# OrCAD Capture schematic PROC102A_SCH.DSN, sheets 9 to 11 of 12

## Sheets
9 10.SMART SWITCH: size C; title: SMART SWITCH
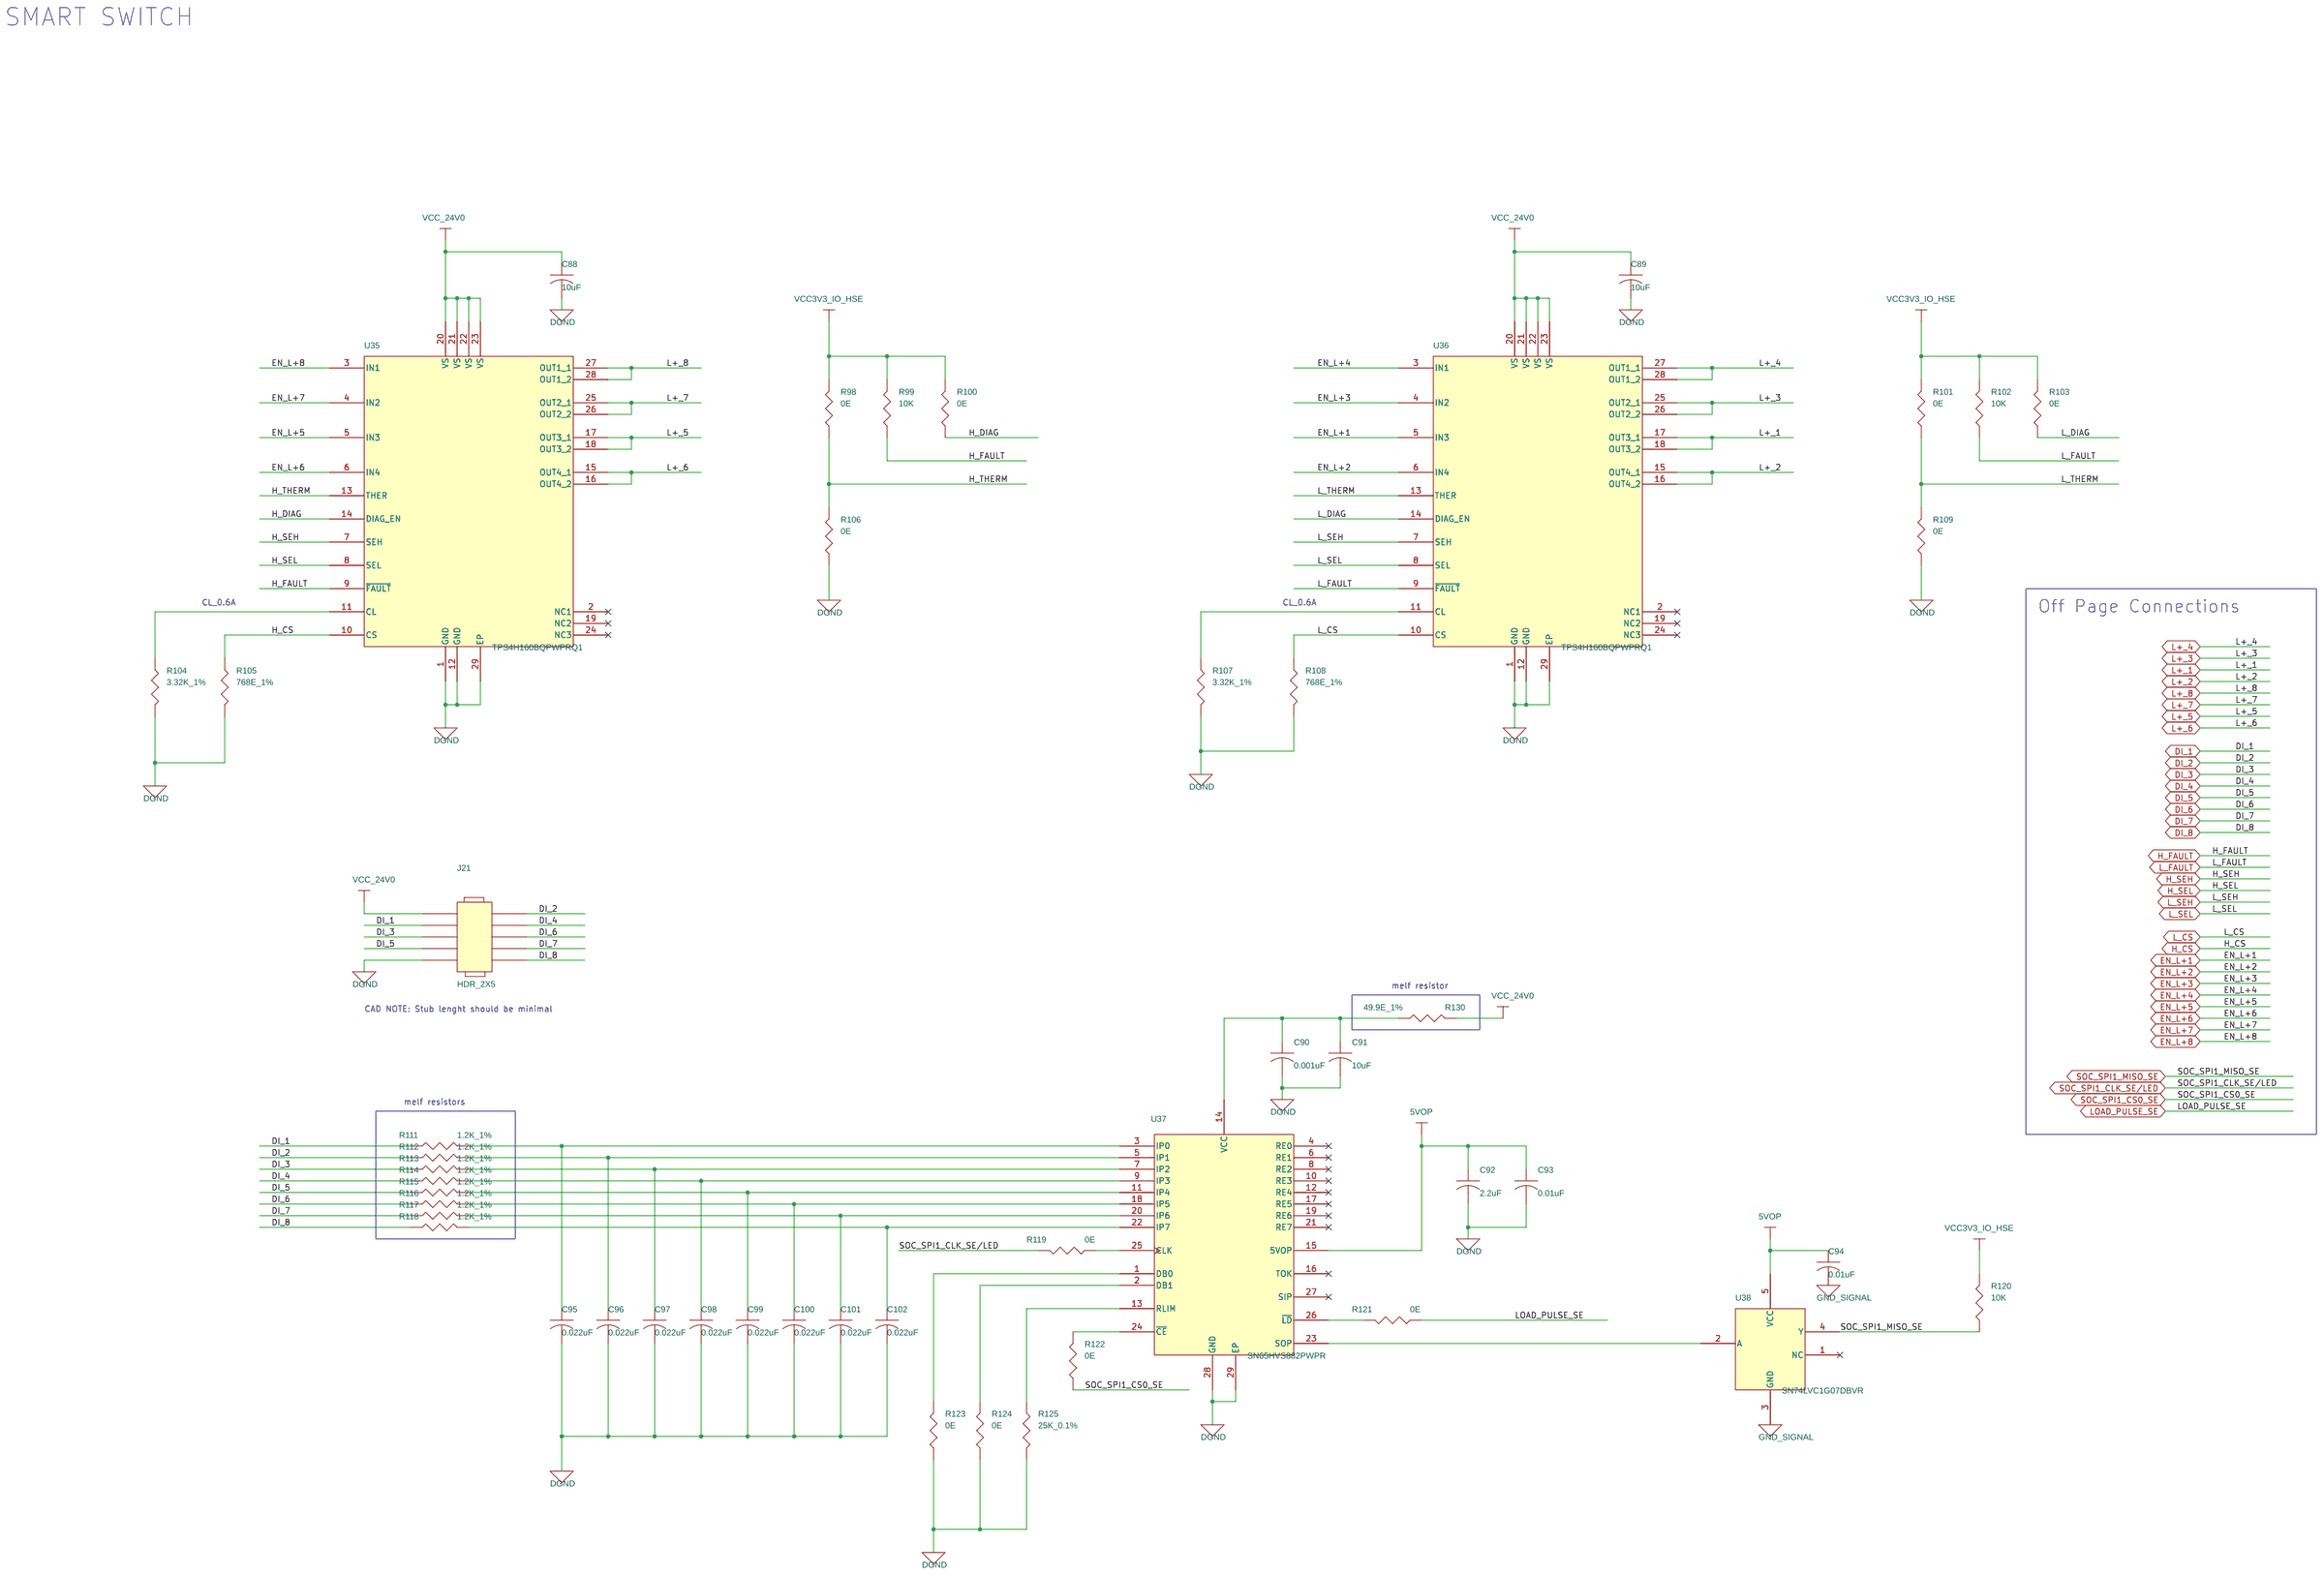
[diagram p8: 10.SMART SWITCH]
10 11.POWER AND ADC SECTION.: size C; title: POWER AND ADC SECTION
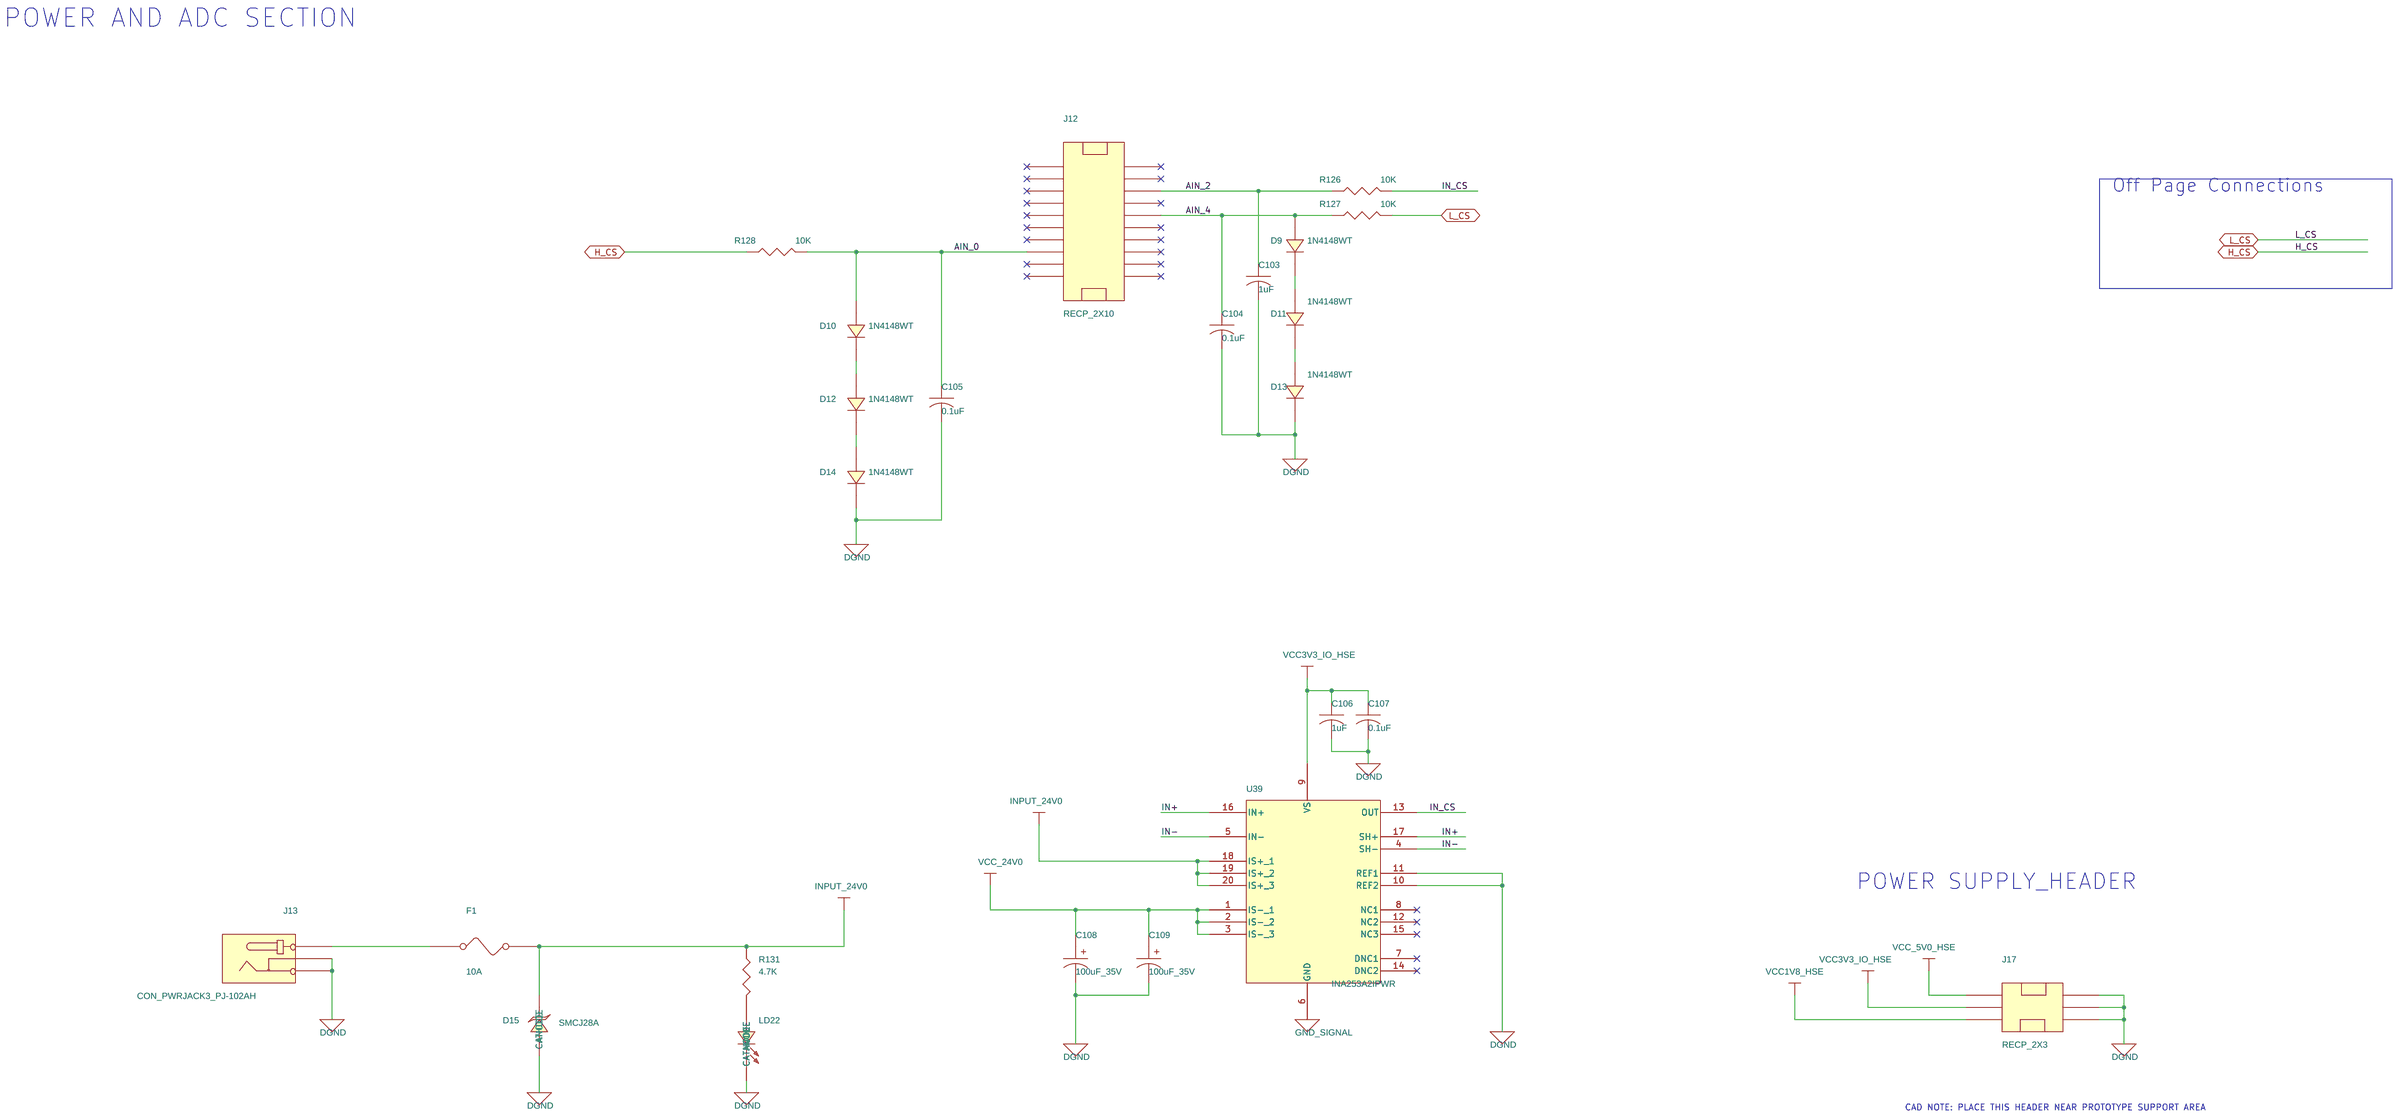
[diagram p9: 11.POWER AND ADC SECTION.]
11 08.IO LINK TRANCIEVER[1:4]: size C; title: IO LINK TRANCIEVER[1:4]
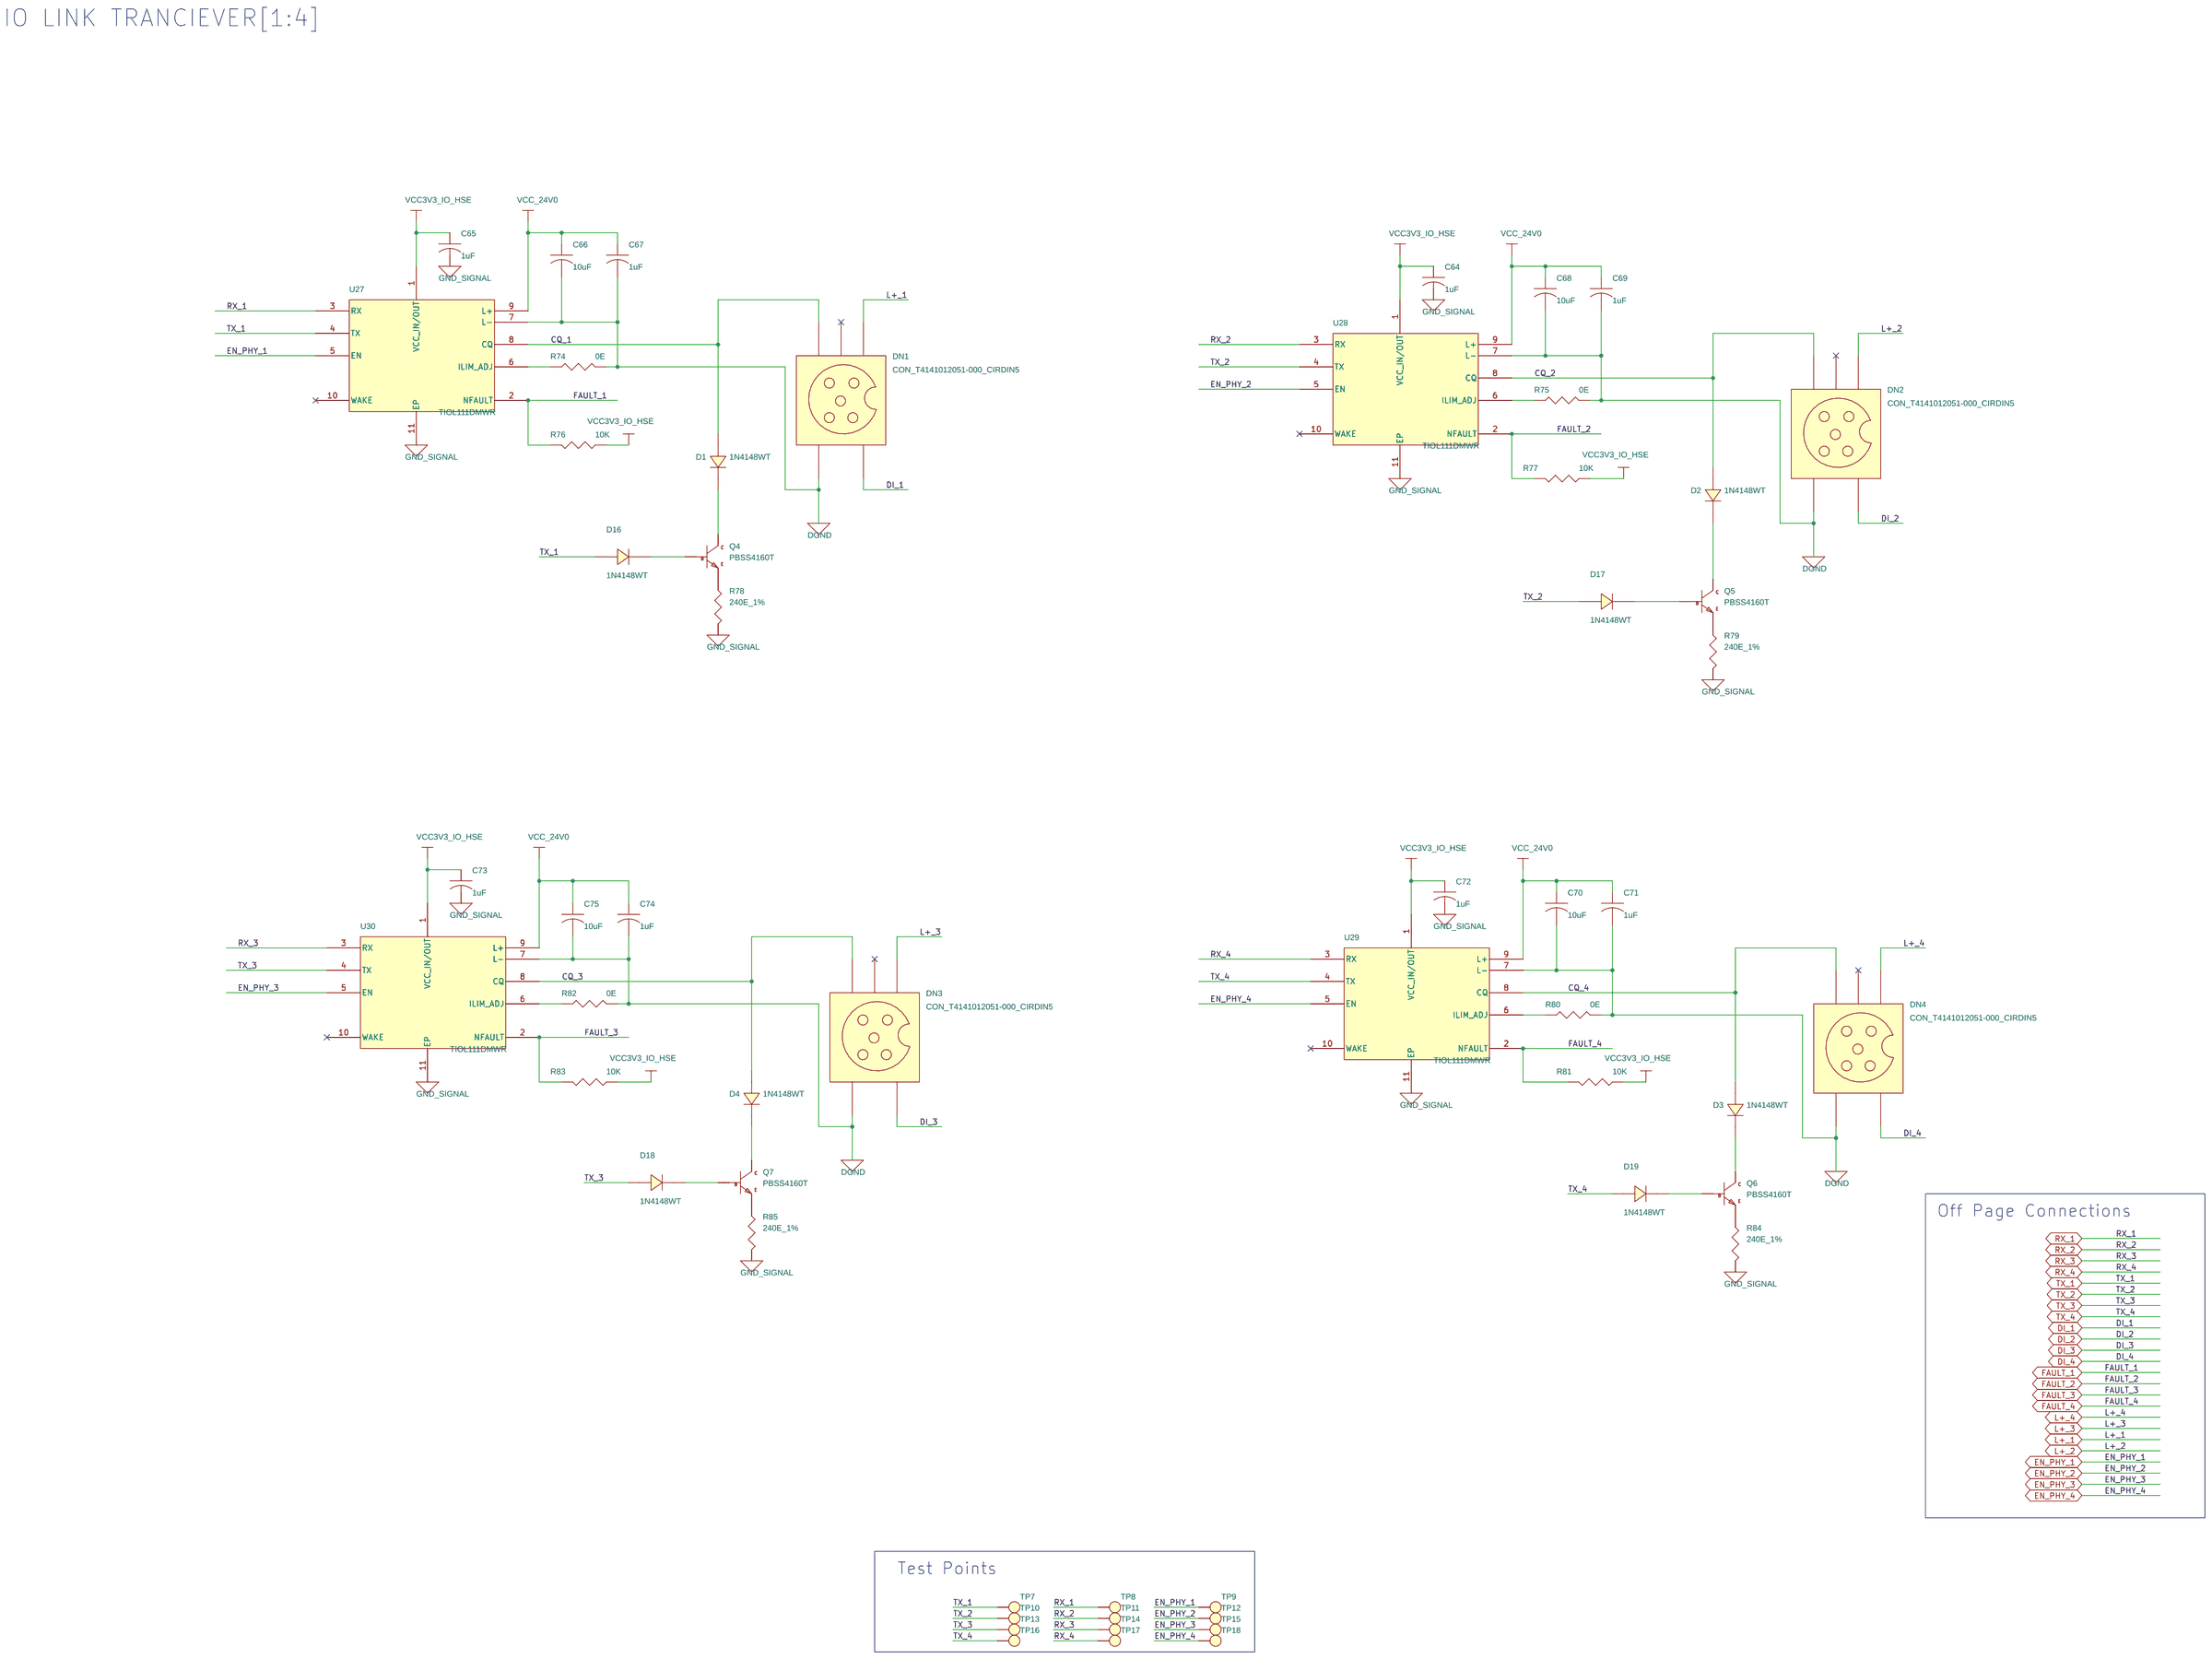
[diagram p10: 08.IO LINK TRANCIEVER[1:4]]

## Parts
sheet 08.IO LINK TRANCIEVER[1:4]
C64  1uF  [CAP0402_0-75]
C65  1uF  [CAP0402_0-75]
C66  10uF  [CAP1206_2]
C67  1uF  [CAP0805_1-5]
C68  10uF  [CAP1206_2]
C69  1uF  [CAP0805_1-5]
C70  10uF  [CAP1206_2]
C71  1uF  [CAP0805_1-5]
C72  1uF  [CAP0402_0-75]
C73  1uF  [CAP0402_0-75]
C74  1uF  [CAP0805_1-5]
C75  10uF  [CAP1206_2]
D1  1N4148WT  [DIO_SOD523]
D2  1N4148WT  [DIO_SOD523]
D3  1N4148WT  [DIO_SOD523]
D4  1N4148WT  [DIO_SOD523]
D16  1N4148WT  [DIO_SOD523]
D17  1N4148WT  [DIO_SOD523]
D18  1N4148WT  [DIO_SOD523]
D19  1N4148WT  [DIO_SOD523]
DN1  CON_T4141012051-000_CIRDIN5  [CON_CIRDIN5_T4141012051_S_S_T_23]
DN2  CON_T4141012051-000_CIRDIN5  [CON_CIRDIN5_T4141012051_S_S_T_23]
DN3  CON_T4141012051-000_CIRDIN5  [CON_CIRDIN5_T4141012051_S_S_T_23]
DN4  CON_T4141012051-000_CIRDIN5  [CON_CIRDIN5_T4141012051_S_S_T_23]
Q4  PBSS4160T  [SOT23-123_1-1]
Q5  PBSS4160T  [SOT23-123_1-1]
Q6  PBSS4160T  [SOT23-123_1-1]
Q7  PBSS4160T  [SOT23-123_1-1]
R74  0E  [RES0402_0-5]
R75  0E  [RES0402_0-5]
R76  10K  [RES0402_0-5]
R77  10K  [RES0402_0-5]
R78  240E_1%  [RES0402_0-5]
R79  240E_1%  [RES0402_0-5]
R80  0E  [RES0402_0-5]
R81  10K  [RES0402_0-5]
R82  0E  [RES0402_0-5]
R83  10K  [RES0402_0-5]
R84  240E_1%  [RES0402_0-5]
R85  240E_1%  [RES0402_0-5]
TP7  TP20_SMD  [TP20_SMD]
TP8  TP20_SMD  [TP20_SMD]
TP9  TP20_SMD  [TP20_SMD]
TP10  TP20_SMD  [TP20_SMD]
TP11  TP20_SMD  [TP20_SMD]
TP12  TP20_SMD  [TP20_SMD]
TP13  TP20_SMD  [TP20_SMD]
TP14  TP20_SMD  [TP20_SMD]
TP15  TP20_SMD  [TP20_SMD]
TP16  TP20_SMD  [TP20_SMD]
TP17  TP20_SMD  [TP20_SMD]
TP18  TP20_SMD  [TP20_SMD]
U27  TIOL111DMWR  [VSON10_19-68_120X100_1]
U28  TIOL111DMWR  [VSON10_19-68_120X100_1]
U29  TIOL111DMWR  [VSON10_19-68_120X100_1]
U30  TIOL111DMWR  [VSON10_19-68_120X100_1]
sheet 10.SMART SWITCH
C88  10uF  [CAP1206_2]
C89  10uF  [CAP1206_2]
C90  0.001uF  [CAP0805_1]
C91  10uF  [CAP1206_2]
C92  2.2uF  [CAP0805_1-5]
C93  0.01uF  [CAP0402_0-75]
C94  0.01uF  [CAP0402_0-75]
C95  0.022uF  [CAP0603_1]
C96  0.022uF  [CAP0603_1]
C97  0.022uF  [CAP0603_1]
C98  0.022uF  [CAP0603_1]
C99  0.022uF  [CAP0603_1]
C100  0.022uF  [CAP0603_1]
C101  0.022uF  [CAP0603_1]
C102  0.022uF  [CAP0603_1]
J21  HDR_2X5  [HDR_5X2_100_S_T_8-6]
R98  0E  [RES0402_0-5]
R99  10K  [RES0402_0-5]
R100  0E  [RES0402_0-5]
R101  0E  [RES0402_0-5]
R102  10K  [RES0402_0-5]
R103  0E  [RES0402_0-5]
R104  3.32K_1%  [RES0402_0-5]
R105  768E_1%  [RES0402_0-5]
R106  0E  [RES0402_0-5]
R107  3.32K_1%  [RES0402_0-5]
R108  768E_1%  [RES0402_0-5]
R109  0E  [RES0402_0-5]
R111  1.2K_1%  [RES_MELF0102_1-1]
R112  1.2K_1%  [RES_MELF0102_1-1]
R113  1.2K_1%  [RES_MELF0102_1-1]
R114  1.2K_1%  [RES_MELF0102_1-1]
R115  1.2K_1%  [RES_MELF0102_1-1]
R116  1.2K_1%  [RES_MELF0102_1-1]
R117  1.2K_1%  [RES_MELF0102_1-1]
R118  1.2K_1%  [RES_MELF0102_1-1]
R119  0E  [RES0402_0-5]
R120  10K  [RES0402_0-5]
R121  0E  [RES0402_0-5]
R122  0E  [RES0402_0-5]
R123  0E  [RES0402_0-5]
R124  0E  [RES0402_0-5]
R125  25K_0.1%  [RES0402_1]
R130  49.9E_1%  [RES_MELF0102_1-1]
U35  TPS4H160BQPWPRQ1  [HTSSOP28_LM5175-Q1_180X390_1-2]
U36  TPS4H160BQPWPRQ1  [HTSSOP28_LM5175-Q1_180X390_1-2]
U37  SN65HVS882PWPR  [ETSSOP28_SN65HVS885_390X180_1-2]
U38  SN74LVC1G07DBVR  [SOT23-5]
sheet 11.POWER AND ADC SECTION.
C103  1uF  [CAP0402_0-75]
C104  0.1uF  [CAP0402_0-75]
C105  0.1uF  [CAP0402_0-75]
C106  1uF  [CAP0402_0-75]
C107  0.1uF  [CAP0402_0-75]
C108  100uF_35V  [CAPAE_DCASE_6-1]
C109  100uF_35V  [CAPAE_DCASE_6-1]
D9  1N4148WT  [DIO_SOD523]
D10  1N4148WT  [DIO_SOD523]
D11  1N4148WT  [DIO_SOD523]
D12  1N4148WT  [DIO_SOD523]
D13  1N4148WT  [DIO_SOD523]
D14  1N4148WT  [DIO_SOD523]
D15  SMCJ28A  [DIO_SMC]
F1  10A  [FUSE_397_410X110_SMD_2-9]
J12  RECP_2X10  [RECPT_2X10_68683-310_S_T_7-1]
J13  CON_PWRJACK3_PJ-102AH  [CON_PWRJACK3_PJ-102AH_P_R_T_11]
J17  RECP_2X3  [RECPT_2X3_PPTC032LFBN_S_T_8-5]
LD22  150060VS75000  [LED_150060SS75000_70X40_SMD_0-8]
R126  10K  [RES0603_0-5]
R127  10K  [RES0603_0-5]
R128  10K  [RES0603_0-5]
R131  4.7K  [RES0805_0-75]
U39  INA253A2IPWR  [TSSOP20_25-59_260X180_1-2]

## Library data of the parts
C64 C65 C72 C73 C103 C106 = CAP: CAP CERAMIC 1uF 10V 20% X5R 0402; Chkd/date: MANIRAJA/210820; Crtd /date: ALVY/190820; Custom_Duty: 15%; Customs_HS_Code: 85322990; Distributor_name: DIGIKEY; Distributor_part_number: 732-7489-1-ND; Footprint Path: Y:\MIS_DATABASE\Library\ALTIUM_TOOL\PCB_FOOTPRINTS\Altium_Footprint_Lib.PcbLib; Height: 0.55MM; Library Path: Y:\MIS_DATABASE\Library\ALTIUM_TOOL\SCHEMATICS_PARTS\MS_DISCRETE_Library.schlib; Mfr_name: WURTH ELECTRONICS; Mfr_part_number: 885012105012; Mistral Part No: 120020080009-R; Package: 0402; Part_type: CAPACITORS\CERAMIC; Project: AM64x_EVM_BRD; RoHS: RoHS; Temperature: -55°C+85°C; Tolerance: 20%; Voltage: 10V; Wattage: NA; Weight: 0.65mg; Datasheet: Y:\MIS_DATABASE\DATASHEETS\CAPACITORS\885012105012.PDF
C66 C68 C70 C75 C88 C89 C91 = CAP: CAP CERAMIC 10uF 50V 10% X5R AUTO 1206; Chkd/date: MANIRAJA/261018; Crtd /date: ALVY/261018; Custom_Duty: 15%; Customs_HS_Code: 85322990; Distributor_name: DIGIKEY; Distributor_part_number: 490-12456-1-ND; Footprint Path: Y:\MIS_DATABASE\Library\ALTIUM_TOOL\PCB_FOOTPRINTS\Altium_Footprint_Lib.PcbLib; Height: 1.80MM; Library Path: Y:\MIS_DATABASE\Library\ALTIUM_TOOL\SCHEMATICS_PARTS\MS_DISCRETE_Library.schlib; Mfr_name: MURATA; Mfr_part_number: GRT31CR61H106KE01L; Mistral Part No: 120011060019-R; Package: 1206; Part_type: CAPACITORS\CERAMIC; Project: LRDE_ABCMV2_MB; RoHS: RoHS; Temperature: -55°C+85°C; Tolerance: 10%; Voltage: 50V; Wattage: NA; Weight: 16.2mg; Datasheet: Y:\MIS_DATABASE\DATASHEETS\CAPACITORS\GRT31CR61H106KE01L.PDF
C67 C69 C71 C74 = CAP: CAP CERAMIC 1uF 50V 10% X7R 0805; Chkd/date: MANIRAJA/100920; Crtd /date: ALVY/100920; Custom_Duty: 15%; Customs_HS_Code: 85322990; Distributor_name: DIGIKEY; Distributor_part_number: 732-7678-1-ND; Footprint Path: Y:\MIS_DATABASE\Library\ALTIUM_TOOL\PCB_FOOTPRINTS\Altium_Footprint_Lib.PcbLib; Height: 1.35MM; Library Path: Y:\MIS_DATABASE\Library\ALTIUM_TOOL\SCHEMATICS_PARTS\MS_DISCRETE_Library.schlib; Mfr_name: WURTH ELECTRONICS; Mfr_part_number: 885012207103; Mistral Part No: 120011010018-R; Package: 0805; Part_type: CAPACITORS\CERAMIC; Project: AM64x-IO LINK BRD; RoHS: RoHS; Temperature: -55°C+125°C; Tolerance: 10%; Voltage: 50V; Wattage: NA; Weight: 36mg; Datasheet: Y:\MIS_DATABASE\DATASHEETS\CAPACITORS\885012207103.PDF
D1-D4 D9-D14 D16-D19 = DIODE: DIODE SWITCH 75V 10mA SOD523; Chkd/date: SUHAS/041010; Crtd /date: MAZHAR/110210; Custom_Duty: 15%; Customs_HS_Code: 85412900; Distributor_name: DIGIKEY; Distributor_part_number: 1N4148WTCT-ND; Height: 0.70MM; Mfr_name: FAIRCHILD; Mistral Part No: 130010020017-R; Package: SOD523; Part_type: DIODE\SWITCHING; Project: NPOL_PREAMP; RoHS: RoHS; Temperature: -55°C+150°C; Tolerance: 20%; Voltage: 75V; Weight: NA; Datasheet: Y:\MIS_DATABASE\DATASHEETS\DISCRETES\DIODES\1N4148WT-F.PDF
DN1-DN4 = CON_T4143012051_CIRDIN5_S: CON CIRCULAR 5POS FEMALE ST TH; Chkd/date: MANIRAJA/280820; Crtd /date: ALVY/280820; Custom_Duty: 24%; Customs_HS_Code: 85369090; Distributor_name: DIGIKEY; Distributor_part_number: A126851-ND; Footprint Path: Y:\MIS_DATABASE\Library\ALTIUM_TOOL\PCB_FOOTPRINTS\Altium_Footprint_Lib.PcbLib; Height: 23.00MM; Library Path: Y:\MIS_DATABASE\Library\ALTIUM_TOOL\SCHEMATICS_PARTS\MS_CONNECTOR_Library.schlib; Mfr_name: TE CONNECTIVITY; Mfr_part_number: T4141012051-000; Mistral Part No: 150020080008-R; Package: THRU-HOLE; Part_type: CONNECTOR\CIRDIN; Project: AM64x_EVM_TESTJIG_BRD; RoHS: RoHS; Temperature: -40°C+85°C; Tolerance: NA; Voltage: NA; Wattage: NA; Weight: 16500mg; Datasheet: Y:\MIS_DATABASE\DATASHEETS\CONNECTORS\T41410120X1-000.PDF
Q4-Q7 = NPN_123_SOT23-3: TRANSISTOR NPN 60V 1A SOT23-3; Chkd/date: MANIRAJA/220720; Crtd /date: ALVY/210720; Custom_Duty: 15%; Customs_HS_Code: 85412900; Distributor_name: DIGIKEY; Distributor_part_number: 1727-3939-1-ND; Footprint Path: Y:\MIS_DATABASE\Library\ALTIUM_TOOL\PCB_FOOTPRINTS\Altium_Footprint_Lib.PcbLib; Height: 1.10MM; Library Path: Y:\MIS_DATABASE\Library\ALTIUM_TOOL\SCHEMATICS_PARTS\MS_TRANSISTOR_Library.schlib; Mfr_name: NXP SEMICONDUCTORS; Mfr_part_number: PBSS4160T,215; Mistral Part No: 130020070017-R; Package: SOT23-3; Part_type: TRANSISTOR\BIPOLAR; Project: AM64x-IO LINK BRD; RoHS: RoHS; Temperature: -65°C+150°C; Tolerance: NA; Voltage: NA; Wattage: NA; Weight: 8mg; Datasheet: Y:\MIS_DATABASE\DATASHEETS\DISCRETES\TRANSISTORS_FETS\PBSS4160T.PDF
R74 R75 R80 R82 = RESISTOR: RES 0E 1/16W JUMPER 0402; Chkd/date: VASANTHA/201216; Crtd /date: MUDDU/190810; Custom_Duty: 15%; Customs_HS_Code: 85332119; Distributor_name: DIGIKEY; Distributor_part_number: 541-0.0JCT-ND; Footprint Path: Y:\MIS_DATABASE\Library\ALTIUM_TOOL\PCB_FOOTPRINTS\Altium_Footprint_Lib.PcbLib; Height: 0.40MM; Library Path: Y:\MIS_DATABASE\Library\ALTIUM_TOOL\SCHEMATICS_PARTS\MS_DISCRETE_Library.schlib; Mfr_name: VISHAY; Mfr_part_number: CRCW04020000Z0ED; Mistral Part No: 110010080019-R; Package: 0402; Part_type: RESISTORS\FIXED; Project: PB_BUGBASE; RoHS: RoHS; Temperature: -55°C+155°C; Tolerance: NA; Voltage: NA; Wattage: 1/16W; Weight: 0.65mg; Datasheet: Y:\MIS_DATABASE\DATASHEETS\RESISTORS\CRCW0603.PDF
R76 R77 R81 R83 R99 R102 R120 = RESISTOR: RES 10K 1/16W 5% 0402; Chkd/date: VASANTHA/061216; Crtd /date: MAZHAR/230805; Custom_Duty: 15%; Customs_HS_Code: 85332119; Distributor_name: DIGIKEY; Distributor_part_number: 311-10KJRCT-ND; Footprint Path: Y:\MIS_DATABASE\Library\ALTIUM_TOOL\PCB_FOOTPRINTS\Altium_Footprint_Lib.PcbLib; Height: 0.40MM; Library Path: Y:\MIS_DATABASE\Library\ALTIUM_TOOL\SCHEMATICS_PARTS\MS_DISCRETE_Library.schlib; Mfr_name: YAGEO AMERICA; Mfr_part_number: RC0402JR-0710KL; Mistral Part No: 110011060021-R; Package: 0402; Part_type: RESISTORS\FIXED; Project: HSE; RoHS: RoHS; Temperature: -55°C+155°C; Tolerance: 5%; Voltage: NA; Wattage: 1/16W; Weight: 0.65mg; Datasheet: Y:\MIS_DATABASE\DATASHEETS\RESISTORS\RCXXXXL-SER_MAR18.PDF
R78 R79 R84 R85 = RESISTOR: RES 240E 1/10W 1% 0402; Chkd/date: MAZHAR/150611; Crtd /date: BAVISH/020611; Custom_Duty: 15%; Customs_HS_Code: 85332119; Distributor_name: DIGIKEY; Distributor_part_number: P240LCT-ND; Footprint Path: Y:\MIS_DATABASE\Library\ALTIUM_TOOL\PCB_FOOTPRINTS\Altium_Footprint_Lib.PcbLib; Height: 0.40MM; Library Path: Y:\MIS_DATABASE\Library\ALTIUM_TOOL\SCHEMATICS_PARTS\MS_DISCRETE_Library.schlib; Mfr_name: PANASONIC-ECG; Mfr_part_number: ERJ-2RKF2400X; Mistral Part No: 110011060017-R; Package: 0402; Part_type: RESISTORS\FIXED; Project: AM4515_EVM_LCD; RoHS: RoHS; Temperature: -55°C+155°C; Tolerance: 1%; Voltage: NA; Wattage: 1/10W; Weight: 0.8mg; Datasheet: Y:\MIS_DATABASE\DATASHEETS\RESISTORS\PAN-ERJSER_NOV17.PDF
TP7-TP18 = TESTPOINT: TESTPOINT CIR 20 SMD; Chkd/date: SHREESHAIL/171006; Crtd /date: MAZHAR/171006; Custom_Duty: NA; Customs_HS_Code: NA; Distributor_name: NA; Distributor_part_number: NA; Footprint Path: Y:\MIS_DATABASE\Library\ALTIUM_TOOL\PCB_FOOTPRINTS\Altium_Footprint_Lib.PcbLib; Height: NA; Library Path: Y:\MIS_DATABASE\Library\ALTIUM_TOOL\SCHEMATICS_PARTS\MS_DISCRETE_Library.schlib; MECHANICAL 3D STEP FILE: NA; Mfr_name: LOCAL; Mistral Part No: NA; Package: SMD; Project: BT MODULE_CSRBC04; RoHS: NA; Temperature: NA; Tolerance: NA; Voltage: NA; Wattage: NA; Weight: NA; Datasheet: NA
U27-U30 = TIOL111_VSON10: IC IO-LINK DEVICE TRANSCEIVER WITH INTEGRATED SURGE PROTECTION VSON10; Chkd/date: MANIRAJA/210720; Crtd /date: ALVY/170720; Custom_Duty: 15%; Customs_HS_Code: 85423100; Distributor_name: DIGIKEY; Distributor_part_number: 296-49943-1-ND; Footprint Path: Y:\MIS_DATABASE\Library\ALTIUM_TOOL\PCB_FOOTPRINTS\Altium_Footprint_Lib.PcbLib; Height: 1.00MM; Library Path: Y:\MIS_DATABASE\Library\ALTIUM_TOOL\SCHEMATICS_PARTS\MS_MISCINTERFACE_Library.schlib; Mfr_name: TEXAS INSTRUMENTS; Mistral Part No: 141020070002-R; Package: VSON10; Part_type: ICS\INTERFACE\TRANSCEIVER; Project: AM64x-GP_EVM BRD; RoHS: RoHS; Temperature: -40°C+125°C; Tolerance: NA; Voltage: NA; Wattage: NA; Weight: 19mg; Datasheet: Y:\MIS_DATABASE\DATASHEETS\ICS\DIGITAL\BUSTRANSCEIVER\TIOL111.PDF
C90 = CAP: CAP CER 1000PF 50V X7R 0805; Chkd/date: USMAN/100812; Crtd /date: CHAITHANYA/080812; Custom_Duty: 15%; Customs_HS_Code: 85322990; Distributor_name: NA; Distributor_part_number: NA; Footprint Path: Y:\MIS_DATABASE\Library\ALTIUM_TOOL\PCB_FOOTPRINTS\Altium_Footprint_Lib.PcbLib; Height: 0.88MM; Library Path: Y:\MIS_DATABASE\Library\ALTIUM_TOOL\SCHEMATICS_PARTS\MS_DISCRETE_Library.schlib; Mfr_name: YAGEO AMERICA; Mfr_part_number: CC0805KRX7R9BB102; Mistral Part No: 120012080013-R; Package: 0805; Part_type: CAPACITORS\CERAMIC; Project: NPOL_FEP; RoHS: RoHS; Temperature: -55°C+125°C; Tolerance: 10%; Voltage: 50V; Wattage: NA; Weight: 5.5mg; Datasheet: Y:\MIS_DATABASE\DATASHEETS\CAPACITORS\C0603T-X7R-SER.PDF
C92 = CAP: CAP CERAMIC 2.2uF 25V 10% X7R 0805; Chkd/date: MANIRAJA/170820; Crtd /date: ALVY/170820; Custom_Duty: 15%; Customs_HS_Code: 85322990; Distributor_name: DIGIKEY; Distributor_part_number: 732-7673-1-ND; Footprint Path: Y:\MIS_DATABASE\Library\ALTIUM_TOOL\PCB_FOOTPRINTS\Altium_Footprint_Lib.PcbLib; Height: 1.45MM; Library Path: Y:\MIS_DATABASE\Library\ALTIUM_TOOL\SCHEMATICS_PARTS\MS_DISCRETE_Library.schlib; Mfr_name: WURTH ELECTRONICS; Mfr_part_number: 885012207079; Mistral Part No: 120009090012-R; Package: 0805; Part_type: CAPACITORS\CERAMIC; Project: AM64x_EVM_BRD; RoHS: RoHS; Temperature: -55°C+125°C; Tolerance: 10%; Voltage: 25V; Wattage: NA; Weight: 5.5mg; Datasheet: Y:\MIS_DATABASE\DATASHEETS\CAPACITORS\885012207079.PDF
C93 C94 = CAP: CAP CERAMIC 0.01uF 25V 10% X7R 0402; Chkd/date: MANIRAJA/170820; Crtd /date: ALVY/170820; Custom_Duty: 15%; Customs_HS_Code: 85322990; Distributor_name: DIGIKEY; Distributor_part_number: 732-7545-1-ND; Footprint Path: Y:\MIS_DATABASE\Library\ALTIUM_TOOL\PCB_FOOTPRINTS\Altium_Footprint_Lib.PcbLib; Height: 0.55MM; Library Path: Y:\MIS_DATABASE\Library\ALTIUM_TOOL\SCHEMATICS_PARTS\MS_DISCRETE_Library.schlib; Mfr_name: WURTH ELECTRONICS; Mfr_part_number: 885012205050; Mistral Part No: 120011090040-R; Package: 0402; Part_type: CAPACITORS\CERAMIC; Project: AM64x_EVM_BRD; RoHS: RoHS; Temperature: -55°C+125°C; Tolerance: 10%; Voltage: 25V; Wattage: NA; Weight: 0.65mg; Datasheet: Y:\MIS_DATABASE\DATASHEETS\CAPACITORS\885012205050.PDF
C95-C102 = CAP: CAP CERAMIC 0.022uF 100V 10% X7R 0603; Chkd/date: MAZHAR/280508; Crtd /date: USMAN/200508; Custom_Duty: 15%; Customs_HS_Code: 85322990; Distributor_name: DIGIKEY; Distributor_part_number: 490-3284-1-ND; Footprint Path: Y:\MIS_DATABASE\Library\ALTIUM_TOOL\PCB_FOOTPRINTS\Altium_Footprint_Lib.PcbLib; Height: 0.90MM; Library Path: Y:\MIS_DATABASE\Library\ALTIUM_TOOL\SCHEMATICS_PARTS\MS_DISCRETE_Library.schlib; Mfr_name: MURATA; Mfr_part_number: GRM188R72A223KAC4D; Mistral Part No: 120009030035-R; Package: 0603; Part_type: CAPACITORS\CERAMIC; Project: KMB; RoHS: RoHS; Temperature: -55°C+125°C; Tolerance: 10%; Voltage: 100V; Wattage: NA; Weight: 6.3mg; Datasheet: Y:\MIS_DATABASE\DATASHEETS\CAPACITORS\GRM188R72A223KAC4D.PDF
J21 = HEADER_5X2: CON HDR 2X5 2.54MM PITCH ST TH; Chkd/date: VASANTHA/220317; Crtd /date: MANIRAJA/210317; Custom_Duty: 24%; Customs_HS_Code: 85369090; Distributor_name: DIGIKEY; Distributor_part_number: 609-3243-ND; Height: 8.58MM; Mfr_name: FCI; Mfr_part_number: 67997-410HLF; Mistral Part No: 150015100040-R; Package: THRU-HOLE; Part_type: CONNECTOR\HEADERS; Project: CYPHY_ROADKILL; RoHS: RoHS; Temperature: NA; Tolerance: NA; Voltage: NA; Wattage: NA; Weight: NA; Datasheet: Y:\MIS_DATABASE\DATASHEETS\CONNECTORS\67997.PDF
R98 R100 R101 R103 R106 R109 R119 R121-R124 = RESISTOR: RES 0E 1/16W JUMPER 0402; Chkd/date: VASANTHA/201216; Crtd /date: MUDDU/190810; Custom_Duty: 15%; Customs_HS_Code: 85332119; Distributor_name: DIGIKEY; Distributor_part_number: 541-0.0JCT-ND; Footprint Path: Y:\MIS_DATABASE\Library\ALTIUM_TOOL\PCB_FOOTPRINTS\Altium_Footprint_Lib.PcbLib; Height: 0.40MM; Library Path: Y:\MIS_DATABASE\Library\ALTIUM_TOOL\SCHEMATICS_PARTS\MS_DISCRETE_Library.schlib; Mfr_name: VISHAY; Mfr_part_number: CRCW04020000Z0ED; Mistral Part No: 110010080019-R; Package: 0402; Part_type: RESISTORS\FIXED; Project: PB_BUGBASE; RoHS: RoHS; SIGNAL_MODEL: RESISTOR_RES0402_22E_1%_22E_1%; Temperature: -55°C+155°C; Tolerance: NA; Voltage: NA; Wattage: 1/16W; Weight: 0.65mg; Datasheet: Y:\MIS_DATABASE\DATASHEETS\RESISTORS\CRCW0603.PDF
R104 R107 = RESISTOR: RES 3.32K 1/10W 1% 0402; Chkd/date: MANIRAJA/190619; Crtd /date: ALVY/180619; Custom_Duty: 15%; Customs_HS_Code: 85332119; Distributor_name: DIGIKEY; Distributor_part_number: P3.32KLCT-ND; Footprint Path: Y:\MIS_DATABASE\Library\ALTIUM_TOOL\PCB_FOOTPRINTS\Altium_Footprint_Lib.PcbLib; Height: 0.40MM; Library Path: Y:\MIS_DATABASE\Library\ALTIUM_TOOL\SCHEMATICS_PARTS\MS_DISCRETE_Library.schlib; Mfr_name: PANASONIC-ECG; Mfr_part_number: ERJ-2RKF3321X; Mistral Part No: 110019060037-R; Package: 0402; Part_type: RESISTORS\FIXED; Project: BRUKER_SD820_COMMONDO; RoHS: RoHS; Temperature: -55°C+155°C; Tolerance: 1%; Voltage: NA; Wattage: 1/10W; Weight: 0.8mg; Datasheet: Y:\MIS_DATABASE\DATASHEETS\RESISTORS\PAN-ERJSER_NOV17.PDF
R105 R108 = RESISTOR: RES 768E 1/10W 1% 0402; Chkd/date: SUHAS/270910; Crtd /date: MAZHAR/161009; Custom_Duty: 15%; Customs_HS_Code: 85332119; Distributor_name: DIGIKEY; Distributor_part_number: P768LCT-ND; Footprint Path: Y:\MIS_DATABASE\Library\ALTIUM_TOOL\PCB_FOOTPRINTS\Altium_Footprint_Lib.PcbLib; Height: 0.40MM; Library Path: Y:\MIS_DATABASE\Library\ALTIUM_TOOL\SCHEMATICS_PARTS\MS_DISCRETE_Library.schlib; Mfr_name: PANASONIC-ECG; Mfr_part_number: ERJ-2RKF7680X; Mistral Part No: 110009100012-R; Package: 0402; Part_type: RESISTORS\FIXED; Project: BUG_BASE-II; RoHS: RoHS; Temperature: -55°C+155°C; Tolerance: 1%; Voltage: NA; Wattage: 1/10W; Weight: 0.8mg; Datasheet: Y:\MIS_DATABASE\DATASHEETS\RESISTORS\PAN-ERJSER_NOV17.PDF
R111-R118 = RESISTOR: RES 1.2K 0.3W 1% AUTO 0102 MELF; Chkd/date: JEBRAN/260315; Crtd /date: NAVEED/310714; Custom_Duty: 15%; Customs_HS_Code: 85332119; Distributor_name: DIGIKEY; Distributor_part_number: MMU-1.2KCCT-ND; Footprint Path: Y:\MIS_DATABASE\Library\ALTIUM_TOOL\PCB_FOOTPRINTS\Altium_Footprint_Lib.PcbLib; Height: 1.10MM; Library Path: Y:\MIS_DATABASE\Library\ALTIUM_TOOL\SCHEMATICS_PARTS\MS_DISCRETE_Library.schlib; Mfr_name: VISHAY; Mfr_part_number: MMU01020C1201FB300; Mistral Part No: 110014070066-R; Package: MELF; Part_type: RESISTORS\FIXED; Project: AGIS_POM; RoHS: RoHS; Temperature: -55°C+155°C; Tolerance: 1%; Voltage: NA; Wattage: 0.3W; Weight: 8mg; Datasheet: Y:\MIS_DATABASE\DATASHEETS\RESISTORS\MMU01020.PDF
R125 = RESISTOR: RES 25K 1/20W 0.1% 0402; Chkd/date: MANIRAJA/290719; Crtd /date: ALVY/290719; Custom_Duty: 15%; Customs_HS_Code: 85332119; Distributor_name: DIGIKEY; Distributor_part_number: 541-1903-1-ND; Footprint Path: Y:\MIS_DATABASE\Library\ALTIUM_TOOL\PCB_FOOTPRINTS\Altium_Footprint_Lib.PcbLib; Height: 0.84MM; Library Path: Y:\MIS_DATABASE\Library\ALTIUM_TOOL\SCHEMATICS_PARTS\MS_DISCRETE_Library.schlib; Mfr_name: VISHAY; Mfr_part_number: PNM0402E2502BST1; Mistral Part No: 110019070028-R; Package: 0402; Part_type: RESISTORS\FIXED; Project: NPOL_UAIS_LPA; RoHS: RoHS; Temperature: -55°C+155°C; Tolerance: 0.1%; Voltage: NA; Wattage: 1/20W; Weight: 120mg; Datasheet: Y:\MIS_DATABASE\DATASHEETS\RESISTORS\PNM_VISHAY-SEP18.PDF
R130 = RESISTOR: RES 49.9E 0.3W 1% AUTO 0102 MELF; Chkd/date: MANIRAJA/280720; Crtd /date: ALVY/240720; Custom_Duty: 15%; Customs_HS_Code: 85332119; Distributor_name: DIGIKEY; Distributor_part_number: MMU-49.9CCT-ND; Footprint Path: Y:\MIS_DATABASE\Library\ALTIUM_TOOL\PCB_FOOTPRINTS\Altium_Footprint_Lib.PcbLib; Height: 1.10MM; Library Path: Y:\MIS_DATABASE\Library\ALTIUM_TOOL\SCHEMATICS_PARTS\MS_DISCRETE_Library.schlib; Mfr_name: VISHAY; Mfr_part_number: MMU01020C4999FB300; Mistral Part No: 110020070019-R; Package: MELF; Part_type: RESISTORS\FIXED; Project: AM64x-IO LINK BRD; RoHS: RoHS; Temperature: -55°C+155°C; Tolerance: 1%; Voltage: NA; Wattage: 0.3W; Weight: 8mg; Datasheet: Y:\MIS_DATABASE\DATASHEETS\RESISTORS\MMU01020.PDF
U35 U36 = TPS4H160-Q1_HTSSOP28: IC 40V 160mE 4-CHANNEL SMART HIGH-SIDE SWITCH HTSSOP28; Chkd/date: MANIRAJA/210720; Crtd /date: ALVY/170720; Custom_Duty: 15%; Customs_HS_Code: 85423100; Distributor_name: DIGIKEY; Distributor_part_number: 296-44711-1-ND; Footprint Path: Y:\MIS_DATABASE\Library\ALTIUM_TOOL\PCB_FOOTPRINTS\Altium_Footprint_Lib.PcbLib; Height: 1.20MM; Library Path: Y:\MIS_DATABASE\Library\ALTIUM_TOOL\SCHEMATICS_PARTS\MS_MISCPOWER_Library.schlib; Mfr_name: TEXAS INSTRUMENTS; Mistral Part No: 142020070006-R; Package: HTSSOP28; Part_type: ICS\POWER; Project: AM64x-GP_EVM BRD; RoHS: RoHS; Temperature: -40°C+125°C; Tolerance: NA; Voltage: NA; Wattage: NA; Weight: 176.5mg; Datasheet: Y:\MIS_DATABASE\DATASHEETS\ICS\POWER\TPS4H160.PDF
U37 = SN65HVS882PWPR_HTSSOP28: IC 8-DIGITAL I/P SERIALIZER HTSSOP28; Chkd/date: MANIRAJA/280817; Crtd /date: MANIRAJA/280817; Custom_Duty: 15%; Customs_HS_Code: 85423100; Distributor_name: DIGIKEY; Distributor_part_number: 296-23432-1-ND; Height: 1.20MM; Mfr_name: TEXAS INSTRUMENTS; Mistral Part No: 141017080029-R; Package: HTSSOP28; Part_type: ICS\INTERFACE; Project: TI_MAXIE_CPB; RoHS: RoHS; Temperature: -40°C+125°C; Tolerance: NA; Voltage: NA; Wattage: NA; Weight: 118.5mg; Datasheet: Y:\MIS_DATABASE\DATASHEETS\ICS\INTERFACE\SN65HVS882.PDF
U38 = SN74LVC1G07DBVR_SOT23-5: IC SINGLE BUFFER/DRIVER SOT23-5; Chkd/date: MAZHAR/200208; Crtd /date: USMAN/200208; Custom_Duty: 15%; Customs_HS_Code: 85423100; Distributor_name: DIGIKEY; Distributor_part_number: 296-8485-1-ND; Footprint Path: Y:\MIS_DATABASE\Library\ALTIUM_TOOL\PCB_FOOTPRINTS\Altium_Footprint_Lib.PcbLib; Height: 1.45MM; Junction to Board °C/W: 62; Junction to Case °C/W: 164; Mfr_name: TEXAS INSTRUMENTS; Mistral Part No: 141009030405-R; Part_type: ICS\INTERFACE\LINE DRIVER; Project: MIB; RoHS: Sb/ Br FREE; Datasheet: Y:\MIS_DATABASE\DATASHEETS\ICS\INTERFACE\SN74LVC1G07.PDF
C104 C105 C107 = CAP: CAP CERAMIC 0.1uF 25V 20% X5R 0402; Alt_Mfr_name: YAGEO AMERICA; Alt_Mfr_part_number: CC0402KRX5R8BB104; Chkd/date: MANIRAJA/170820; Crtd /date: ALVY/170820; Custom_Duty: 15%; Customs_HS_Code: 85322990; Distributor_name: DIGIKEY; Distributor_part_number: 732-7495-1-ND; Footprint Path: Y:\MIS_DATABASE\Library\ALTIUM_TOOL\PCB_FOOTPRINTS\Altium_Footprint_Lib.PcbLib; Height: 0.55MM; Library Path: Y:\MIS_DATABASE\Library\ALTIUM_TOOL\SCHEMATICS_PARTS\MS_DISCRETE_Library.schlib; Mfr_name: WURTH ELECTRONICS; Mfr_part_number: 885012105018; Mistral Part No: 120020080003-R; Package: 0402; Part_type: CAPACITORS\CERAMIC; Project: AM64x_EVM_BRD; RoHS: RoHS; Temperature: -55°C+85°C; Tolerance: 20%; Voltage: 25V; Wattage: NA; Weight: 0.65mg; Datasheet: Y:\MIS_DATABASE\DATASHEETS\CAPACITORS\885012105018.PDF
C108 C109 = CAP_POL: CAP ELECTROLYTIC 100uF 35V 20% DCASE_6666; Chkd/date: MANIRAJA/280918; Crtd /date: ALVY/270918; Custom_Duty: 15%; Customs_HS_Code: 85322990; Distributor_name: DIGIKEY; Distributor_part_number: PCE5016CT-ND; Footprint Path: Y:\MIS_DATABASE\Library\ALTIUM_TOOL\PCB_FOOTPRINTS\Altium_Footprint_Lib.PcbLib; Height: 6.10MM; Library Path: Y:\MIS_DATABASE\Library\ALTIUM_TOOL\SCHEMATICS_PARTS\MS_DISCRETE_Library.schlib; Mfr_name: PANASONIC-ECG; Mfr_part_number: EEE-FT1V101AP; Mistral Part No: 120018090055-R; Package: DCASE_6666; Part_type: CAPACITORS\ELECTROLYTIC; Project: TI_J7_SVB-DUT; RoHS: RoHS; Temperature: -55°C+105°C; Tolerance: 20%; Voltage: 35V; Wattage: NA; Weight: NA; Datasheet: Y:\MIS_DATABASE\DATASHEETS\CAPACITORS\FTV-SER.PDF
D15 = DIODE_TVS: DIODE TVS 1500W 28V UNIDIR SMC; Chkd/date: MAZHAR/041010; Crtd /date: BAVISH/041010; Custom_Duty: 15%; Customs_HS_Code: 85412900; Distributor_name: DIGIKEY; Distributor_part_number: SMCJ28-ND; Height: 2.62MM; Mfr_name: LITTLE FUSE; Mistral Part No: 130010100001-R; Package: SMC; Part_type: DIODE\TVS; Project: ITS; RoHS: RoHS; Temperature: -55°C+150°C; Tolerance: NA; Voltage: 28V; Wattage: 1500W; Weight: NA; Datasheet: Y:\MIS_DATABASE\DATASHEETS\DISCRETES\DIODES\SMCJ-LITT.PDF
F1 = FUSE: FUSE 10A 60V FAST SMD; Chkd/date: RAGESH/151010; Crtd /date: MAZHAR/220907; Distributor_name: DIGIKEY; Distributor_part_number: TR2/1025FA10-R-ND; Height: 2.90MM; Mfr_name: COOPER BUSSMANN; Mfr_part_number: 1025FA10-R; Mistral Part No: 130009030821-R; Package: SMD; Project: SMART VIEW_NVR; RoHS: RoHS; Voltage: 60V; Datasheet: Y:\MIS_DATABASE\DATASHEETS\MISC\FUSE\1025FA-SER.PDF
J12 = RECP_10X2: CON RECP 2X10 2.54MM PITCH ST TH; Chkd/date: MANIRAJA/220720; Crtd /date: ALVY/210720; Custom_Duty: 24%; Customs_HS_Code: 85369090; Distributor_name: DIGIKEY; Distributor_part_number: 609-3576-ND; Footprint Path: Y:\MIS_DATABASE\Library\ALTIUM_TOOL\PCB_FOOTPRINTS\Altium_Footprint_Lib.PcbLib; Height: 7.01MM; Library Path: Y:\MIS_DATABASE\Library\ALTIUM_TOOL\SCHEMATICS_PARTS\MS_CONNECTOR_Library.schlib; Mfr_name: AMPHENOL FCI; Mfr_part_number: 68683-310LF; Mistral Part No: 150020070010-R; Package: THRU-HOLE; Part_type: CONNECTOR\RECEPTACLE; Project: AM64x-GP_EVM BRD; RoHS: RoHS; Temperature: -65°C+125°C; Tolerance: NA; Voltage: NA; Wattage: NA; Weight: NA; Datasheet: Y:\MIS_DATABASE\DATASHEETS\CONNECTORS\68683-XX.PDF
J13 = CON_PWRJACK3_PJ-102A: CON POWER JACK 3POS MALE RT TH; Chkd/date: MANIRAJA/220720; Crtd /date: ALVY/210720; Custom_Duty: 24%; Customs_HS_Code: 85369090; Distributor_name: DIGIKEY; Distributor_part_number: CP-102AH-ND; Footprint Path: Y:\MIS_DATABASE\Library\ALTIUM_TOOL\PCB_FOOTPRINTS\Altium_Footprint_Lib.PcbLib; Height: 11.00MM; Library Path: Y:\MIS_DATABASE\Library\ALTIUM_TOOL\SCHEMATICS_PARTS\MS_CONNECTOR_Library.schlib; Mfr_name: CUI INC; Mfr_part_number: PJ-102AH; Mistral Part No: 150020070011-R; Package: THRU-HOLE; Part_type: CONNECTOR\JACK; Project: AM64x-GP_EVM BRD; RoHS: RoHS; Temperature: -25°C+85°C; Tolerance: NA; Voltage: NA; Wattage: NA; Weight: 1800mg; Datasheet: Y:\MIS_DATABASE\DATASHEETS\CONNECTORS\PJ-102AH.PDF
J17 = RECP_3X2: CON RECP 2X3 2.54MM PITCH ST TH; Chkd/date: MANIRAJA/090119; Crtd /date: ALVY/090119; Custom_Duty: 24%; Customs_HS_Code: 85369090; Distributor_name: DIGIKEY; Distributor_part_number: S7071-ND; Footprint Path: Y:\MIS_DATABASE\Library\ALTIUM_TOOL\PCB_FOOTPRINTS\Altium_Footprint_Lib.PcbLib; Height: 8.50MM; Library Path: Y:\MIS_DATABASE\Library\ALTIUM_TOOL\SCHEMATICS_PARTS\MS_CONNECTOR_Library.schlib; Mfr_name: SULLINS CONNECTOR; Mfr_part_number: PPTC032LFBN-RC; Mistral Part No: 150019010001-R; Package: THRU-HOLE; Part_type: CONNECTOR\RECEPTACLE; Project: TI_MAXIE_BREAKOUT CARD; RoHS: RoHS; Temperature: -40°C+105°C; Tolerance: NA; Voltage: NA; Wattage: NA; Weight: NA; Datasheet: Y:\MIS_DATABASE\DATASHEETS\CONNECTORS\XPXCXX2LFBN-SER.PDF
LD22 = DIODE_LED: DIODE LED BRIGHT GREEN SMD; Chkd/date: MANIRAJA/220720; Crtd /date: ALVY/210720; Custom_Duty: 24%; Customs_HS_Code: 85439000; Distributor_name: DIGIKEY; Distributor_part_number: 732-4980-1-ND; Footprint Path: Y:\MIS_DATABASE\Library\ALTIUM_TOOL\PCB_FOOTPRINTS\Altium_Footprint_Lib.PcbLib; Height: 0.80MM; Library Path: Y:\MIS_DATABASE\Library\ALTIUM_TOOL\SCHEMATICS_PARTS\MS_OPTO_Library.schlib; Mfr_name: WURTH ELECTRONICS; Mistral Part No: 130020070019-R; Package: SMD; Part_type: OPTO\LED; Project: AM64x-IO LINK BRD; RoHS: RoHS; Temperature: -40°C+85°C; Tolerance: NA; Voltage: NA; Wattage: NA; Weight: 25mg; Datasheet: Y:\MIS_DATABASE\DATASHEETS\DISCRETES\LEDS\150060VS75000.PDF
R126-R128 = RESISTOR: RES 10K 1/10W 5% 0603; Chkd/date: NAVEED/190814; Crtd /date: MUDDU/160210; Custom_Duty: 15%; Customs_HS_Code: 85332119; Distributor_name: DIGIKEY; Distributor_part_number: 541-10KGCT-ND; Footprint Path: Y:\MIS_DATABASE\Library\ALTIUM_TOOL\PCB_FOOTPRINTS\Altium_Footprint_Lib.PcbLib; Height: 0.50MM; Library Path: Y:\MIS_DATABASE\Library\ALTIUM_TOOL\SCHEMATICS_PARTS\MS_DISCRETE_Library.schlib; Mfr_name: VISHAY; Mfr_part_number: CRCW060310K0JNEA; Mistral Part No: 110010020016-R; Package: 0603; Part_type: RESISTORS\FIXED; Project: NPOL_PREAMP; RoHS: RoHS; Temperature: -55°C+155°C; Tolerance: 5%; Voltage: NA; Wattage: 1/10W; Weight: 2mg; Datasheet: Y:\MIS_DATABASE\DATASHEETS\RESISTORS\CRCW0603.PDF
R131 = RESISTOR: RES 4.7K 1/8W 5% 0805; Chkd/date: MAZHAR/090608; Crtd /date: USMAN/090608; Custom_Duty: 15%; Customs_HS_Code: 85332119; Distributor_name: DIGIKEY; Distributor_part_number: P4.7KACT-ND; Footprint Path: Y:\MIS_DATABASE\Library\ALTIUM_TOOL\PCB_FOOTPRINTS\Altium_Footprint_Lib.PcbLib; Height: 0.70MM; Library Path: Y:\MIS_DATABASE\Library\ALTIUM_TOOL\SCHEMATICS_PARTS\MS_DISCRETE_Library.schlib; Mfr_name: PANASONIC-ECG; Mfr_part_number: ERJ-6GEYJ472V; Mistral Part No: 110009030790-R; Package: 0805; Part_type: RESISTORS\FIXED; Project: KMB; RoHS: RoHS; Temperature: -55°C+155°C; Tolerance: 5%; Voltage: NA; Wattage: 1/8W; Weight: 4mg; Datasheet: Y:\MIS_DATABASE\DATASHEETS\RESISTORS\PAN-ERJSER_NOV17.PDF
U39 = INA253A_TSSOP20: IC HIGH VOLTAGE BI-DIR ZERO-DRIFT CURRENT-SHUNT MONITOR WITH INTEGRATED 2mE SHUNT RESISTOR TSSOP20; Chkd/date: MANIRAJA/220720; Crtd /date: ALVY/210720; Custom_Duty: 15%; Customs_HS_Code: 85423100; Distributor_name: DIGIKEY; Distributor_part_number: 296-INA253A2IPWRTR-ND; Footprint Path: Y:\MIS_DATABASE\Library\ALTIUM_TOOL\PCB_FOOTPRINTS\Altium_Footprint_Lib.PcbLib; Height: 1.20MM; Library Path: Y:\MIS_DATABASE\Library\ALTIUM_TOOL\SCHEMATICS_PARTS\MS_MISCPOWER_Library.schlib; Mfr_name: TEXAS INSTRUMENTS; Mistral Part No: 142020070008-R; Package: TSSOP20; Part_type: ICS\POWER\AMPLIFIER; Project: AM64x-GP_EVM BRD; RoHS: RoHS; Temperature: -40°C+125°C; Tolerance: NA; Voltage: NA; Wattage: NA; Weight: 89.1mg; Datasheet: Y:\MIS_DATABASE\DATASHEETS\ICS\POWER\INA253A.PDF

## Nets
5VOP: C92.1 C93.1 C94.1 U37.15(5VOP) U38.5(VCC)
DGND: C64.2 C65.2 C66.2 C67.2 C68.2 C69.2 C70.2 C71.2 C72.2 C73.2 C74.2 C75.2 C88.2 C89.2 C90.2 C91.2 C92.2 C93.2 C94.2 C95.2 C96.2 C97.2 C98.2 C99.2 C100.2 C101.2 C102.2 C103.2 C104.2 C105.2 C106.2 C107.2 C108.2 C109.2 D13.1(K) D14.1(K) D15.2(ANODE) DN1.3 DN2.3 DN3.3 DN4.3 J13.2 J13.3 J17.2 J17.4 J17.6 J21.9 LD22.1(CATHODE) R74.2 R75.2 R78.2 R79.2 R80.2 R82.2 R84.2 R85.2 R104.2 R105.2 R106.1 R107.2 R108.2 R109.1 R123.1 R124.1 R125.2 U27.7(L-) U27.11(EP) U28.7(L-) U28.11(EP) U29.7(L-) U29.11(EP) U30.7(L-) U30.11(EP) U35.1(GND) U35.12(GND) U35.29(EP) U36.1(GND) U36.12(GND) U36.29(EP) U37.28(GND) U37.29(EP) U38.3(GND) U39.6(GND) U39.10(REF2) U39.11(REF1) ; also on sheet 5 6 7 8 12
VCC1V8_HSE: J17.5 ; also on sheet 5 8
VCC3V3_IO_HSE: C64.1 C65.1 C72.1 C73.1 C106.1 C107.1 J17.3 R76.2 R77.2 R81.2 R83.2 R98.2 R99.1 R100.2 R101.2 R102.1 R103.2 R120.1 U27.1(VCC_IN/OUT) U28.1(VCC_IN/OUT) U29.1(VCC_IN/OUT) U30.1(VCC_IN/OUT) U39.9(VS) ; also on sheet 5 6 7 8 12
VCC_5V0_HSE: J17.1 ; also on sheet 5 8
VCC_24V0: C66.1 C67.1 C68.1 C69.1 C70.1 C71.1 C74.1 C75.1 C88.1 C89.1 C108.1 C109.1 J21.1 R130.2 U27.9(L+) U28.9(L+) U29.9(L+) U30.9(L+) U35.20(VS) U35.21(VS) U35.22(VS) U35.23(VS) U36.20(VS) U36.21(VS) U36.22(VS) U36.23(VS) U39.1(IS-) U39.2(IS-) U39.3(IS-) ; also on sheet 8 12
AIN_0: C105.1 D10.2(A) J12.15 R128.2
AIN_2: C103.1 J12.6 R126.1
AIN_4: C104.1 D9.2(A) J12.10 R127.1
CQ_1: D1.2(A) DN1.4 U27.8(CQ)
CQ_2: D2.2(A) DN2.4 U28.8(CQ)
CQ_3: D4.2(A) DN3.4 U30.8(CQ)
CQ_4: D3.2(A) DN4.4 U29.8(CQ)
DI_1: DN1.2 J21.3 R111.1
DI_2: DN2.2 J21.2 R112.1
DI_3: DN3.2 J21.5 R113.1
DI_4: DN4.2 J21.4 R114.1
DI_5: J21.7 R115.1 ; also on sheet 12
DI_6: J21.6 R116.1 ; also on sheet 12
DI_7: J21.8 R117.1 ; also on sheet 12
DI_8: J21.10 R118.1 ; also on sheet 12
EN_L+1: U36.5(IN3) ; also on sheet 6
EN_L+2: U36.6(IN4) ; also on sheet 6
EN_L+3: U36.4(IN2) ; also on sheet 6
EN_L+4: U36.3(IN1) ; also on sheet 6
EN_L+5: U35.5(IN3) ; also on sheet 6
EN_L+6: U35.6(IN4) ; also on sheet 6
EN_L+7: U35.4(IN2) ; also on sheet 6
EN_L+8: U35.3(IN1) ; also on sheet 6
EN_PHY_1: TP9.1(TP) U27.5(EN) ; also on sheet 6
EN_PHY_2: TP12.1(TP) U28.5(EN) ; also on sheet 6
EN_PHY_3: TP15.1(TP) U30.5(EN) ; also on sheet 6
EN_PHY_4: TP18.1(TP) U29.5(EN) ; also on sheet 6
FAULT_1: R76.1 U27.2(NFAULT) ; also on sheet 7
FAULT_2: R77.1 U28.2(NFAULT) ; also on sheet 7
FAULT_3: R83.1 U30.2(NFAULT) ; also on sheet 7
FAULT_4: R81.1 U29.2(NFAULT) ; also on sheet 7
H_CS: R105.1 R128.1 U35.10(CS)
H_DIAG: R100.1 U35.14(DIAG_EN)
H_FAULT: R99.2 U35.9(~{FAULT}) ; also on sheet 7
H_SEH: U35.7(SEH) ; also on sheet 7
H_SEL: U35.8(SEL) ; also on sheet 7
H_THERM: R98.1 R106.2 U35.13(THER)
IN+: U39.16(IN+) U39.17(SH+)
IN-: U39.4(SH-) U39.5(IN-)
IN_CS: R126.2 U39.13(OUT)
INPUT_24V0: D15.1(CATHODE) F1.2 R131.1 U39.18(IS+_1) U39.19(IS+_2) U39.20(IS+_3)
L+_1: DN1.1 U36.17(OUT3_1) U36.18(OUT3_2)
L+_2: DN2.1 U36.15(OUT4_1) U36.16(OUT4_2)
L+_3: DN3.1 U36.25(OUT2_1) U36.26(OUT2_2)
L+_4: DN4.1 U36.27(OUT1_1) U36.28(OUT1_2)
L+_5: U35.17(OUT3_1) U35.18(OUT3_2) ; also on sheet 12
L+_6: U35.15(OUT4_1) U35.16(OUT4_2) ; also on sheet 12
L+_7: U35.25(OUT2_1) U35.26(OUT2_2) ; also on sheet 12
L+_8: U35.27(OUT1_1) U35.28(OUT1_2) ; also on sheet 12
L_CS: R108.1 R127.2 U36.10(CS)
L_DIAG: R103.1 U36.14(DIAG_EN)
L_FAULT: R102.2 U36.9(~{FAULT}) ; also on sheet 7
L_SEH: U36.7(SEH) ; also on sheet 7
L_SEL: U36.8(SEL) ; also on sheet 7
L_THERM: R101.1 R109.2 U36.13(THER)
LOAD_PULSE_SE: R121.1 ; also on sheet 7
RX_1: TP8.1(TP) U27.3(RX) ; also on sheet 6
RX_2: TP11.1(TP) U28.3(RX) ; also on sheet 6
RX_3: TP14.1(TP) U30.3(RX) ; also on sheet 6
RX_4: TP17.1(TP) U29.3(RX) ; also on sheet 6
SOC_SPI1_CLK_SE/LED: R119.2 ; also on sheet 7 8
SOC_SPI1_CS0_SE: R122.1 ; also on sheet 7
SOC_SPI1_MISO_SE: R120.2 U38.4(Y) ; also on sheet 7
TX_1: D16.2(A) TP7.1(TP) U27.4(TX) ; also on sheet 6
TX_2: D17.2(A) TP10.1(TP) U28.4(TX) ; also on sheet 6
TX_3: D18.2(A) TP13.1(TP) U30.4(TX) ; also on sheet 6
TX_4: D19.2(A) TP16.1(TP) U29.4(TX) ; also on sheet 6
N16728800: R104.1 U35.11(CL)
N16729761: R107.1 U36.11(CL)
N16731521: C95.1 R111.2 U37.3(IP0)
N16731525: C96.1 R112.2 U37.5(IP1)
N16731545: C97.1 R113.2 U37.7(IP2)
N16731549: C98.1 R114.2 U37.9(IP3)
N16731553: C99.1 R115.2 U37.11(IP4)
N16731557: C100.1 R116.2 U37.18(IP5)
N16731561: C101.1 R117.2 U37.20(IP6)
N16731565: C102.1 R118.2 U37.22(IP7)
N16731823: R123.2 U37.1(DB0)
N16731831: R124.2 U37.2(DB1)
N16731839: R122.2 U37.24(~{CE})
N16731843: R125.1 U37.13(RLIM)
N16732073: C90.1 C91.1 R130.1 U37.14(VCC)
N16732201: U37.23(SOP) U38.2(A)
N16798390: R121.2 U37.26(~{LD})
N16811368: F1.1 J13.1
N16812824: D10.1(K) D12.2(A)
N16812834: D12.1(K) D14.2(A)
N16813069: D9.1(K) D11.2(A)
N16813071: D11.1(K) D13.2(A)
N16970041: R82.1 U30.6(ILIM_ADJ)
N16970059: D4.1(K) Q7.3(COLLECTOR)
N17109412: R119.1 U37.25(CLK)
N17175087: R74.1 U27.6(ILIM_ADJ)
N17175103: D1.1(K) Q4.3(COLLECTOR)
N17184096: R75.1 U28.6(ILIM_ADJ)
N17184112: D2.1(K) Q5.3(COLLECTOR)
N17184793: R80.1 U29.6(ILIM_ADJ)
N17184817: D3.1(K) Q6.3(COLLECTOR)
N17219803: LD22.2(ANODE) R131.2
N17284061: Q6.2(EMITTER) R84.1
N17284065: Q5.2(EMITTER) R79.1
N17284066: Q4.2(EMITTER) R78.1
N17284068: Q7.2(EMITTER) R85.1
N17284137: D16.1(K) Q4.1(BASE)
N17284170: D17.1(K) Q5.1(BASE)
N17284203: D18.1(K) Q7.1(BASE)
N17284241: D19.1(K) Q6.1(BASE)

Not connected (* = marked no-connect by the designer): DN1 5*; DN2 5*; DN3 5*; DN4 5*; J12 1* 2* 3* 4* 5* 7* 8* 9* 11* 12* 13* 14* 16* 17* 18* 19* 20*; U27 10(WAKE)*; U28 10(WAKE)*; U29 10(WAKE)*; U30 10(WAKE)*; U35 2(NC1)* 19(NC2)* 24(NC3)*; U36 2(NC1)* 19(NC2)* 24(NC3)*; U37 4(RE0)* 6(RE1)* 8(RE2)* 10(RE3)* 12(RE4)* 16(TOK)* 17(RE5)* 19(RE6)* 21(RE7)* 27(SIP)*; U38 1(NC)*; U39 7(DNC1)* 8(NC1)* 12(NC2)* 14(DNC2)* 15(NC3)*

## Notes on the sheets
sheet 9
- SMART SWITCH
- CL_0.6A
- CL_0.6A
- Off Page Connections
- melf resistor
- CAD NOTE: Stub lenght should be minimal
- melf resistors
sheet 10
- POWER AND ADC SECTION
- Off Page Connections
- POWER SUPPLY_HEADER
- CAD NOTE: PLACE THIS HEADER NEAR PROTOTYPE SUPPORT AREA
sheet 11
- IO LINK TRANCIEVER[1:4]
- Off Page Connections
- Test Points
